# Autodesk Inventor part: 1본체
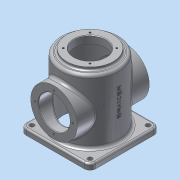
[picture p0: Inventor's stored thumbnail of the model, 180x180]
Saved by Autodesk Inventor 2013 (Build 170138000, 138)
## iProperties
Created: 2015-10
Part Number: 1본체
Material: 알루미늄 6061
Document SubType Name: Modeling
Designer: dgall
Density: 2.71 g/cm^3
Mass: 985.996 g
Surface Area: 1037.34 cm^2
Volume: 363.836 cm^3
Author: dgall
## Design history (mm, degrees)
sketch "스케치1"
  geometry: C1 r 50 at (0, 0); 1 further point
  constraints: 1 centre point, 1 coincident
  dimensions: "d0" = 100 diameter of C1
extrude "돌출1" new body sketch "스케치1" distance "d2" = 120; taper "d3" = 0 deg
sketch "스케치2"
  geometry: C1 r 50 at (0, 0) reference; C2 r 40 at (0, 0)
  constraints: 1 centre point, 1 coincident
  dimensions: "d4" = 80 diameter of C2
extrude "돌출2" join sketch "스케치2" distance "d6" = 5; taper "d7" = 0 deg
sketch "스케치3"
  geometry: L1 (-60, 60)-(60, 60); L2 (60, 60)-(60, -60); L3 (60, -60)-(-60, -60); L4 (-60, -60)-(-60, 60); C1 r 50 at (0, 0) reference; 2 further points
  constraints: 8 end point, 2 midpoint, 2 parallel, 2 perpendicular, 1 horizontal, 1 horizontal alignment, 1 vertical alignment
  dimensions: "d8" = 120 distance of L1.start L1.end
extrude "돌출3" join sketch "스케치3" distance "d11" = 10; taper "d12" = 0 deg
fillet "모깎기1" dims "d13" = 10
sketch "스케치4"
  geometry: A1 r 10 centre (-50, -50) between (-60, -50) and (-50, -60) reference; A2 r 10 centre (50, -50) between (50, -60) and (60, -50) reference; A3 r 10 centre (50, 50) between (60, 50) and (50, 60) reference; A4 r 10 centre (-50, 50) between (-50, 60) and (-60, 50) reference
hole "구멍1" sketch "스케치4" at (50, 50), (-50, 50), (-50, -50), (50, -50) diameter "d14" = 8; stored, may be unused: countersink angle "d18" = 90 deg, drill point angle "d20" = 118 deg; dims "d15" = 6, "d16" = 4, "d17" = 2, "d19" = 8
sketch "스케치5"
  geometry: C1 r 40 at (0, 0) reference; C2 r 27 at (0, 0)
  constraints: 1 centre point, 1 coincident
  dimensions: "d21" = 54 diameter of C2
extrude "돌출4" cut sketch "스케치5" distance "d23" = 13; taper "d24" = 0 deg
sketch "스케치6"
  geometry: L1 (-40, 0)-(0, 0); L2 (0, 0)-(-22.981, 22.981); 1 further point
  constraints: 4 end point, 1 coincident, 1 horizontal, 1 horizontal alignment, 1 other
  dimensions: "d26" = 45 deg angle of L1 L2; "d27" = 32.5 distance of L1.end L2.end
hole "구멍2" sketch "스케치6" at (-22.981, 22.981) diameter "d28" = 3.242; stored, may be unused: countersink angle "d32" = 90 deg, drill point angle "d34" = 118 deg; dims "d29" = 8, "d30" = 4, "d31" = 2, "d33" = 10
node "작업 평면1"
sketch "스케치7"
  geometry: L1 (-3.602, 45.113)-(-3.602, 94.887); L2 (-3.602, 94.887)-(3.602, 94.887); L3 (3.602, 94.887)-(3.602, 45.113); L4 (3.602, 45.113)-(-3.602, 45.113); L5 (-50, 0)-(50, 0) reference; 5 further points
  constraints: 3 midpoint, 2 vertical alignment, 1 horizontal alignment, 2 other
  dimensions: "d39" = 70 distance from line of L5 point (0, 70)
feature "엠보싱1" sketch "스케치7" dims "d2" = 120, "d3" = 0, "d13" = 10, "d40" = 0.5, "d41" = 0
sketch "스케치8"
  geometry: C1 r 40 at (0, 60); C2 r 27 at (0, 60); 1 further point
  constraints: 2 centre point, 1 coincident, 1 vertical alignment
  dimensions: "d43" = 60 distance of point (0, 0) C1.centre; "d44" = 80 diameter of C1; "d45" = 54 diameter of C2
extrude "돌출5" join sketch "스케치8" stored distance "d46" = 124; taper "d47" = 0 deg
extrude "돌출6" cut sketch "스케치8" stored distance "d48" = 124; taper "d49" = 0 deg
fillet "모깎기3" dims "d42" = 5
sketch "스케치9"
  geometry: C1 r 27 at (0, 0) reference; 2 further points
  constraints: 1 vertical alignment
  dimensions: "d50" = 32.5 distance of C1.centre point (0, -32.5)
hole "구멍3" sketch "스케치9" at (0, -32.5) diameter "d51" = 3.242; stored, may be unused: countersink angle "d55" = 90 deg, drill point angle "d57" = 118 deg; dims "d52" = 8, "d53" = 4, "d54" = 2, "d56" = 10
sketch "스케치10"
  geometry: C1 r 45 at (0, 0); 1 further point
  constraints: 1 centre point, 1 coincident
  dimensions: "d61" = 90 diameter of C1
extrude "돌출7" cut sketch "스케치10" distance "d63" = 112; taper "d64" = 0 deg
fillet "모깎기2" dims "d25" = 3
chamfer "모따기1" distance "d65" = 1; stored, may be unused: second distance "d66" = 2, angle "d67" = 45 deg
chamfer "모따기2" distance "d68" = 3; stored, may be unused: second distance "d69" = 2, angle "d70" = 45 deg
node "솔리드1"
pattern_circular "원형 패턴1" dims angle "d36" = 360 deg
pattern_circular "원형 패턴2" dims angle "d59" = 360 deg
mirror "대칭1"
